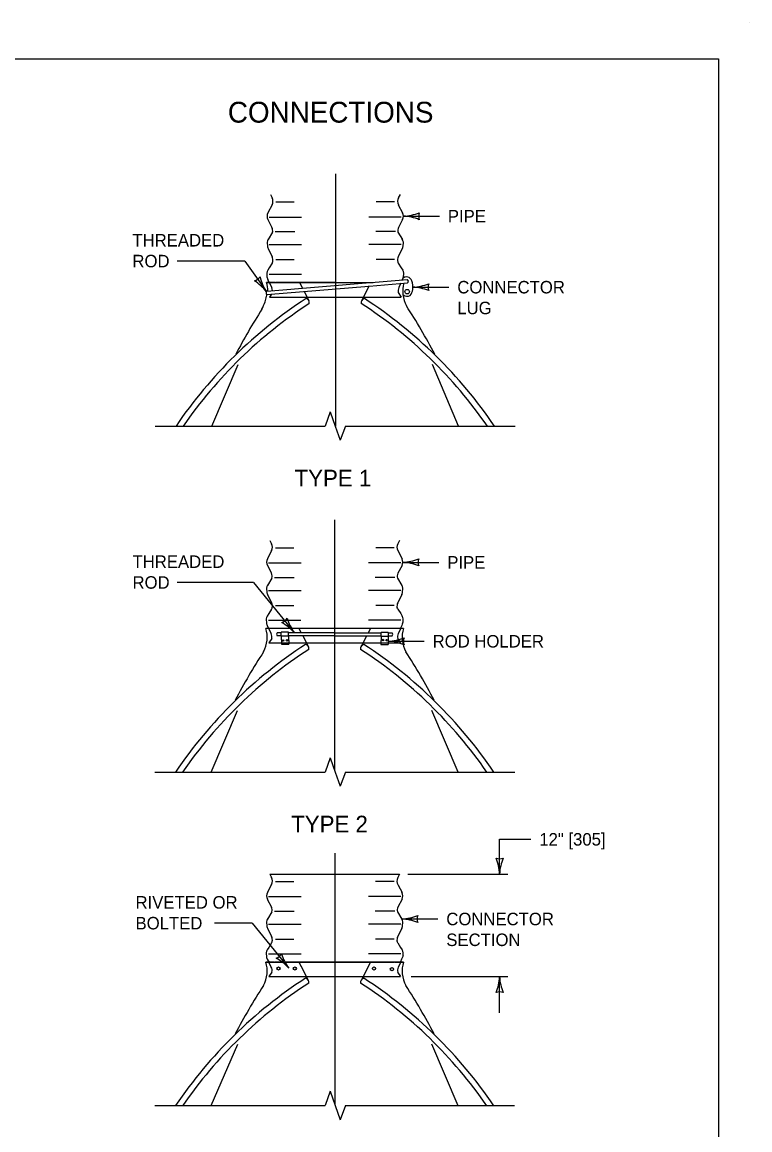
# Model space of a CAD drawing. Extents: x 49991.4 to 50021, y 49987.6 to 50011.4.
# Drawn here: x 50013.4 to 50016.9, y 49993.85 to 49999.18 of the extents above; entities that cross this region are included whole.
import ezdxf

# ---------------------------------------------------------------- set-up
doc = ezdxf.new("R2010")
doc.units = 0
for name, color, linetype in [('Level 1', 7, 'Continuous'), ('Level 2', 7, 'Continuous'), ('Level 3', 7, 'Continuous'), ('Level 4', 7, 'Continuous'), ('Level 5', 7, 'Continuous'), ('Level 6', 7, 'Continuous')]:
    doc.layers.add(name, color=color, linetype=linetype)

msp = doc.modelspace()

# ---------------------------------------------------------------- linework, layer by layer
at = {"layer": 'Level 1'}
for p, q in [((50016.9001, 49999.1756), (50016.9001, 49999.1756)), ((50014.6049, 49998.298), (50014.5842, 49998.2589)), ((50014.5961, 49998.3469), (50014.6049, 49998.3308)), ((50014.6232, 49998.3122), (50014.7113, 49998.3122)), ((50015.1933, 49998.3122), (50015.1048, 49998.3122)), ((50015.2195, 49998.3469), (50015.2111, 49998.3308)), ((50015.2111, 49998.298), (50015.2317, 49998.2589)), ((50014.5842, 49998.2265), (50014.604, 49998.1891)), ((50014.5902, 49998.2388), (50014.7463, 49998.2388)), ((50015.2255, 49998.2388), (50015.0697, 49998.2388)), ((50015.2317, 49998.2265), (50015.2121, 49998.1891)), ((50014.6067, 49998.1655), (50014.5853, 49998.131)), ((50014.6195, 49998.1694), (50014.7132, 49998.1692)), ((50015.1967, 49998.1694), (50015.1031, 49998.1692)), ((50015.2093, 49998.1655), (50015.2309, 49998.131)), ((50014.5854, 49998.0871), (50014.6052, 49998.0475)), ((50014.5902, 49998.107), (50014.746, 49998.107)), ((50015.2255, 49998.107), (50015.0699, 49998.107)), ((50015.2302, 49998.0871), (50015.2111, 49998.0475)), ((50014.6229, 49998.0339), (50014.7111, 49998.0339)), ((50015.1934, 49998.0339), (50015.1048, 49998.0339)), ((50014.5912, 49997.9951), (50014.584, 49997.983)), ((50014.6052, 49998.0165), (50014.5912, 49997.9951)), ((50014.607, 49998.0218), (50014.6078, 49998.024)), ((50015.2089, 49998.0218), (50015.2082, 49998.024)), ((50015.2111, 49998.0165), (50015.2247, 49997.9951)), ((50015.2247, 49997.9951), (50015.2323, 49997.983)), ((50014.5776, 49997.9245), (50015.0795, 49997.9244)), ((50014.5832, 49997.9387), (50014.5903, 49997.9244)), ((50014.5902, 49997.9644), (50014.746, 49997.9644)), ((50015.0803, 49997.9238), (50015.254, 49997.9377)), ((50015.2301, 49997.9387), (50015.2283, 49997.935)), ((50015.2323, 49997.944), (50015.2301, 49997.9387)), ((50015.2363, 49997.9548), (50015.2323, 49997.944)), ((50015.2323, 49997.944), (50015.2323, 49997.944)), ((50014.6183, 49997.9244), (50014.5776, 49997.9244)), ((50014.5776, 49997.9244), (50015.0894, 49997.9244)), ((50014.5793, 49997.8669), (50015.0699, 49997.9068)), ((50014.5798, 49997.8828), (50015.076, 49997.9235)), ((50014.9088, 49997.9244), (50014.6213, 49997.9244)), ((50014.736, 49997.9244), (50014.7506, 49997.8968)), ((50014.7584, 49997.8815), (50014.7815, 49997.8362)), ((50015.0709, 49997.9074), (50015.0344, 49997.8362)), ((50015.0704, 49997.9068), (50015.2553, 49997.9223)), ((50015.076, 49997.9235), (50015.076, 49997.9235)), ((50015.08, 49997.9244), (50015.088, 49997.9244)), ((50014.7724, 49997.854), (50015.0435, 49997.854)), ((50014.3151, 49997.234), (50014.441, 49997.5295)), ((50015.501, 49997.2338), (50015.3747, 49997.5294)), ((50014.5934, 49996.6837), (50014.602, 49996.6675)), ((50014.6204, 49996.6489), (50014.7086, 49996.6489)), ((50015.1905, 49996.6489), (50015.1023, 49996.6489)), ((50015.217, 49996.6837), (50015.2084, 49996.6675)), ((50014.602, 49996.635), (50014.5819, 49996.5957)), ((50015.2084, 49996.635), (50015.2289, 49996.5957)), ((50014.5819, 49996.5634), (50014.6012, 49996.5259)), ((50014.5876, 49996.5756), (50014.7436, 49996.5756)), ((50015.2227, 49996.5756), (50015.067, 49996.5756)), ((50015.2289, 49996.5634), (50015.2094, 49996.5259)), ((50014.604, 49996.5024), (50014.5825, 49996.468)), ((50014.6165, 49996.5063), (50014.7105, 49996.5061)), ((50015.1941, 49996.5063), (50015.1003, 49996.5061)), ((50015.2067, 49996.5024), (50015.2279, 49996.468)), ((50014.5876, 49996.4438), (50014.7436, 49996.4438)), ((50015.2227, 49996.4438), (50015.0672, 49996.4438)), ((50014.5828, 49996.4239), (50014.6023, 49996.3845)), ((50015.2279, 49996.4239), (50015.2082, 49996.3845)), ((50014.5885, 49996.3319), (50014.581, 49996.3199)), ((50014.6023, 49996.3535), (50014.5885, 49996.3319)), ((50014.6047, 49996.3587), (50014.6053, 49996.361)), ((50014.6203, 49996.3708), (50014.7084, 49996.3707)), ((50015.1905, 49996.3708), (50015.1023, 49996.3707)), ((50015.2059, 49996.3587), (50015.2054, 49996.361)), ((50015.2082, 49996.3535), (50015.2224, 49996.3319)), ((50015.2224, 49996.3319), (50015.2296, 49996.3199)), ((50014.5806, 49996.2755), (50014.5875, 49996.2612)), ((50014.5876, 49996.3013), (50014.7434, 49996.3013)), ((50015.2227, 49996.3013), (50015.0672, 49996.3013)), ((50015.2276, 49996.2757), (50015.2213, 49996.2627)), ((50015.2293, 49996.2809), (50015.2276, 49996.2757)), ((50015.2334, 49996.2916), (50015.2293, 49996.2809)), ((50015.2293, 49996.2809), (50015.2293, 49996.2809)), ((50015.2357, 49996.2612), (50014.5749, 49996.2612)), ((50014.6474, 49996.2403), (50014.6295, 49996.2403)), ((50014.6483, 49996.2252), (50014.6295, 49996.2252)), ((50014.6826, 49996.2423), (50014.6481, 49996.2423)), ((50014.6826, 49996.2237), (50014.6481, 49996.2237)), ((50014.6481, 49996.2237), (50014.6492, 49996.186)), ((50014.6826, 49996.2237), (50014.6852, 49996.1859)), ((50014.9065, 49996.2252), (50014.6835, 49996.2252)), ((50014.9055, 49996.2403), (50014.6845, 49996.2403)), ((50014.7335, 49996.2612), (50014.7443, 49996.2403)), ((50014.7518, 49996.2252), (50014.7788, 49996.173)), ((50014.9045, 49996.2252), (50015.0588, 49996.2252)), ((50014.9055, 49996.2403), (50015.1263, 49996.2403)), ((50015.0586, 49996.2252), (50015.0318, 49996.173)), ((50015.0588, 49996.2252), (50015.1276, 49996.2252)), ((50015.0771, 49996.2612), (50015.0663, 49996.2403)), ((50015.1279, 49996.2237), (50015.1271, 49996.1839)), ((50015.1279, 49996.2423), (50015.1629, 49996.2423)), ((50015.1279, 49996.2237), (50015.1629, 49996.2237)), ((50015.1629, 49996.2237), (50015.1622, 49996.1831)), ((50015.1627, 49996.2252), (50015.1812, 49996.2252)), ((50015.1636, 49996.2403), (50015.1812, 49996.2403)), ((50014.6492, 49996.186), (50014.6856, 49996.1857)), ((50014.7695, 49996.1909), (50015.041, 49996.1909)), ((50015.1271, 49996.1839), (50015.1622, 49996.1839)), ((50014.3122, 49995.5705), (50014.438, 49995.8664)), ((50015.4985, 49995.5705), (50015.3722, 49995.8664)), ((50014.5934, 49995.0801), (50015.217, 49995.0801)), ((50014.5938, 49995.0795), (50014.6021, 49995.0635)), ((50015.217, 49995.0801), (50015.2084, 49995.0633)), ((50014.6021, 49995.0309), (50014.582, 49994.9916)), ((50014.6201, 49995.0447), (50014.7085, 49995.0447)), ((50015.1904, 49995.0447), (50015.1021, 49995.0447)), ((50015.2104, 49995.0272), (50015.2288, 49994.9916)), ((50014.5815, 49994.9592), (50014.6009, 49994.9216)), ((50014.5878, 49994.9714), (50014.7436, 49994.9714)), ((50015.2227, 49994.9714), (50015.0672, 49994.9714)), ((50015.2288, 49994.9592), (50015.2093, 49994.9216)), ((50014.6039, 49994.8981), (50014.5827, 49994.8639)), ((50014.6165, 49994.9019), (50014.7101, 49994.9019)), ((50015.194, 49994.9019), (50015.1003, 49994.9019)), ((50015.2066, 49994.8981), (50015.2282, 49994.8639)), ((50014.5878, 49994.8397), (50014.7436, 49994.8397)), ((50015.2227, 49994.8397), (50015.0672, 49994.8397)), ((50014.5827, 49994.8198), (50014.6022, 49994.7804)), ((50015.2278, 49994.8198), (50015.2082, 49994.7804)), ((50014.6022, 49994.7492), (50014.5885, 49994.7275)), ((50014.6045, 49994.7545), (50014.6052, 49994.7563)), ((50014.6201, 49994.7664), (50014.7084, 49994.7664)), ((50015.1904, 49994.7664), (50015.1021, 49994.7664)), ((50015.2059, 49994.7545), (50015.2056, 49994.7563)), ((50015.2082, 49994.7492), (50015.2219, 49994.7275)), ((50014.5885, 49994.7275), (50014.5809, 49994.7155)), ((50014.5878, 49994.6969), (50014.7436, 49994.6969)), ((50015.2227, 49994.6969), (50015.0672, 49994.6969)), ((50015.2219, 49994.7275), (50015.2298, 49994.7155)), ((50015.2292, 49994.6767), (50015.2271, 49994.6713)), ((50015.2336, 49994.6873), (50015.2292, 49994.6767)), ((50015.2292, 49994.6767), (50015.2292, 49994.6767)), ((50014.616, 49994.6572), (50014.5748, 49994.6572)), ((50014.5748, 49994.6572), (50015.1918, 49994.6572)), ((50015.2357, 49994.6572), (50014.6187, 49994.6572)), ((50014.7336, 49994.6572), (50014.7443, 49994.6358)), ((50014.7439, 49994.6371), (50014.7786, 49994.5688)), ((50015.0769, 49994.6572), (50015.0318, 49994.5688)), ((50015.1947, 49994.6572), (50015.2357, 49994.6572)), ((50015.2271, 49994.6713), (50015.2213, 49994.6585)), ((50014.7695, 49994.5868), (50015.041, 49994.5868)), ((50014.3123, 49993.9671), (50014.4391, 49994.2618)), ((50015.4984, 49993.9663), (50015.3722, 49994.2622))]:
    msp.add_line(p, q, dxfattribs=at)
msp.add_lwpolyline([(49999.3835, 49998.9992), (50016.7501, 49998.9992), (50016.7501, 49987.7988), (49999.3835, 49987.7988)], close=True, dxfattribs=at)
for centre, radius in [((50015.2533, 49997.8799), 0.011), ((50014.657, 49996.2031), 0.00375), ((50014.6758, 49996.2038), 0.00375), ((50015.1378, 49996.2052), 0.00375), ((50015.1552, 49996.2045), 0.00375), ((50014.6353, 49994.6258), 0.00763), ((50014.7138, 49994.6258), 0.00763), ((50015.094, 49994.6258), 0.00763), ((50015.1801, 49994.6228), 0.00763)]:
    msp.add_circle(centre, radius, dxfattribs=at)
for centre, radius, start, end in [((50014.5736, 49998.3143), 0.0352, 332.371, 27.6851), ((50015.2424, 49998.3143), 0.0352, 152.3149, 207.629), ((50014.6157, 49998.2427), 0.0352, 152.3604, 207.46), ((50015.2003, 49998.2427), 0.0352, 332.54, 27.6396), ((50014.5723, 49998.1734), 0.0352, 346.8983, 26.3953), ((50015.2437, 49998.1734), 0.0352, 153.6047, 193.1017), ((50014.6157, 49998.1129), 0.0352, 148.1002, 195.4761), ((50014.617, 49998.1029), 0.0352, 179.0002, 206.3871), ((50015.2003, 49998.1129), 0.0352, 344.5239, 31.8998), ((50015.199, 49998.1029), 0.0352, 333.613, 0.9998), ((50014.5735, 49998.032), 0.0352, 346.8983, 26.3953), ((50015.2425, 49998.032), 0.0352, 153.6047, 193.1017), ((50014.6136, 49997.9643), 0.0352, 148.1002, 195.4761), ((50014.5735, 49998.032), 0.0352, 333.8088, 343.22), ((50015.2425, 49998.032), 0.0352, 196.78, 206.1912), ((50015.2024, 49997.9643), 0.0352, 344.5239, 31.8998), ((50014.6149, 49997.9543), 0.0352, 179.0002, 206.3871), ((50015.2505, 49997.9247), 0.0259, 16.8301, 137.3233), ((50015.25, 49997.9297), 0.0092, 304.5117, 64.8853), ((50015.195, 49997.9015), 0.086, 352.6406, 20.9309), ((50014.5858, 49997.8744), 0.0104, 125.5062, 232.8624), ((50014.4342, 49997.8819), 0.1495, 0.1324, 16.4834), ((50014.4304, 49997.8824), 0.1495, 0.1196, 0.1324), ((50015.3818, 49997.8819), 0.1495, 164.8373, 207.8835), ((50015.2323, 49997.8946), 0.0482, 317.2806, 355.0402), ((50015.9737, 49995.9928), 2.2116, 123.0384, 145.8684), ((50015.9737, 49995.9928), 2.1834, 123.0384, 145.3653), ((50014.4304, 49997.8824), 0.1495, 350.4533, 353.7472), ((50014.7632, 49997.8269), 0.0205, 349.5581, 76.5269), ((50015.0528, 49997.8269), 0.0205, 103.4731, 190.4419), ((50013.8423, 49995.9928), 2.1834, 34.6347, 56.9616), ((50013.8423, 49995.9928), 2.2116, 34.1316, 56.9616), ((50015.2523, 49997.8864), 0.0289, 231.0275, 302.1309), ((50016.9089, 49996.2838), 2.7969, 147.2818, 152.4206), ((50012.9071, 49996.2838), 2.7969, 27.5794, 33.1194), ((50014.5709, 49996.6512), 0.0352, 332.371, 27.6851), ((50015.2396, 49996.6512), 0.0352, 152.3149, 207.629), ((50014.613, 49996.5796), 0.0352, 152.3604, 207.46), ((50015.1976, 49996.5796), 0.0352, 332.54, 27.6396), ((50014.5695, 49996.5103), 0.0352, 346.8983, 26.3953), ((50015.241, 49996.5103), 0.0352, 153.6047, 193.1017), ((50014.613, 49996.4498), 0.0352, 148.1002, 195.4761), ((50014.6143, 49996.4398), 0.0352, 179.0002, 206.3871), ((50015.1975, 49996.4498), 0.0352, 344.5239, 31.8998), ((50015.1963, 49996.4398), 0.0352, 333.613, 0.9998), ((50014.5708, 49996.3689), 0.0352, 346.8983, 26.3953), ((50015.2398, 49996.3689), 0.0352, 153.6047, 193.1017), ((50014.5708, 49996.3689), 0.0352, 333.8088, 343.22), ((50015.2398, 49996.3689), 0.0352, 196.78, 206.1912), ((50014.6109, 49996.3012), 0.0352, 148.1002, 195.4761), ((50014.6121, 49996.2912), 0.0352, 179.0002, 206.3871), ((50015.1997, 49996.3012), 0.0352, 344.5239, 31.8998), ((50014.4315, 49996.2188), 0.1495, 332.1165, 16.4834), ((50014.6362, 49996.2328), 0.00996, 132.7323, 227.2677), ((50014.6723, 49996.2329), 0.026, 159.233, 200.767), ((50014.6467, 49996.2329), 0.0372, 345.6586, 14.3414), ((50015.1641, 49996.2329), 0.0372, 165.6586, 194.3414), ((50015.1386, 49996.2329), 0.026, 339.233, 20.767), ((50015.1746, 49996.2328), 0.00996, 312.7323, 47.2677), ((50015.379, 49996.2188), 0.1495, 163.5166, 207.8835), ((50015.971, 49994.3297), 2.2116, 123.0384, 145.8707), ((50014.7604, 49996.1637), 0.0205, 349.5581, 76.5269), ((50015.0501, 49996.1637), 0.0205, 103.4731, 190.4419), ((50013.8396, 49994.3297), 2.2116, 34.1293, 56.9616), ((50015.971, 49994.3297), 2.1834, 123.0384, 145.3677), ((50016.9062, 49994.6207), 2.7969, 146.8806, 152.4206), ((50013.8396, 49994.3297), 2.1834, 34.6323, 56.9616), ((50012.9044, 49994.6207), 2.7969, 27.5794, 33.1194), ((50014.5709, 49995.0469), 0.0352, 332.371, 27.6851), ((50015.2396, 49995.0469), 0.0352, 152.3149, 214.0203), ((50014.6129, 49994.9753), 0.0352, 152.3604, 207.46), ((50015.1975, 49994.9753), 0.0352, 332.54, 27.6396), ((50014.5695, 49994.906), 0.0352, 346.8983, 26.3953), ((50015.241, 49994.906), 0.0352, 153.6047, 193.1017), ((50014.613, 49994.8455), 0.0352, 148.1002, 195.4761), ((50014.6142, 49994.8355), 0.0352, 179.0002, 206.3871), ((50015.1962, 49994.8355), 0.0352, 333.613, 0.9998), ((50015.1981, 49994.8463), 0.0349, 343.0868, 30.4626), ((50014.5707, 49994.7646), 0.0352, 346.8983, 26.3953), ((50014.5707, 49994.7646), 0.0352, 333.8088, 343.22), ((50015.2398, 49994.7646), 0.0352, 153.6047, 193.1017), ((50015.2398, 49994.7646), 0.0352, 196.78, 206.1912), ((50014.6108, 49994.6969), 0.0352, 148.1002, 195.4761), ((50014.6121, 49994.6869), 0.0352, 179.0002, 237.3604), ((50015.1997, 49994.6969), 0.0352, 344.5239, 31.8998), ((50014.4315, 49994.6145), 0.1495, 332.1165, 16.4834), ((50015.379, 49994.6145), 0.1495, 163.5166, 207.8835), ((50015.9709, 49992.7254), 2.2116, 123.0384, 145.843), ((50014.7604, 49994.5595), 0.0205, 349.5581, 76.5269), ((50015.0501, 49994.5595), 0.0205, 103.4731, 190.4419), ((50013.8396, 49992.7254), 2.2116, 34.132, 56.9616), ((50015.9709, 49992.7254), 2.1834, 123.0384, 145.3394), ((50016.9061, 49993.0164), 2.7969, 146.8806, 152.4206), ((50013.8396, 49992.7254), 2.1834, 34.6351, 56.9616), ((50012.9043, 49993.0164), 2.7969, 27.5794, 33.1194)]:
    msp.add_arc(centre, radius, start, end, dxfattribs=at)
msp.add_spline([(50014.5557, 49997.7954), (50014.571, 49997.8314), (50014.5781, 49997.8575)], degree=3, dxfattribs=at)
at = {"layer": 'Level 3'}
for p, q in [((50015.2356, 49998.2427), (50015.409, 49998.2427)), ((50014.4729, 49998.027), (50014.1477, 49998.027)), ((50014.4729, 49998.027), (50014.577, 49997.8799)), ((50015.281, 49997.9015), (50015.4545, 49997.9015)), ((50015.2328, 49996.5786), (50015.4063, 49996.5786)), ((50014.5158, 49996.4819), (50014.1482, 49996.4819)), ((50014.5158, 49996.4819), (50014.7116, 49996.2403)), ((50015.1624, 49996.1991), (50015.3359, 49996.1991)), ((50015.6978, 49995.0801), (50015.6978, 49995.247)), ((50015.6978, 49995.247), (50015.8485, 49995.247)), ((50015.2571, 49995.0801), (50015.7378, 49995.0801)), ((50014.5093, 49994.844), (50014.3278, 49994.844)), ((50014.5093, 49994.844), (50014.6848, 49994.6273)), ((50015.2281, 49994.864), (50015.4016, 49994.864)), ((50015.2721, 49994.5868), (50015.7378, 49994.5868)), ((50015.6978, 49994.4134), (50015.6978, 49994.5868))]:
    msp.add_line(p, q, dxfattribs=at)
for centre, radius, start, end in [((50015.2241, 49998.4754), 0.233, 272.8273, 292.0772), ((50015.3638, 49998.2427), 0.0548, 162.1388, 197.8612), ((50015.2264, 49998.0206), 0.2223, 67.456, 87.6395), ((50014.503, 49997.9845), 0.0548, 287.4334, 323.1557), ((50014.3937, 49997.736), 0.233, 38.1219, 57.3717), ((50014.7636, 49998.0007), 0.2223, 192.7506, 212.9341), ((50015.2695, 49998.1342), 0.233, 272.8273, 292.0772), ((50015.2719, 49997.6794), 0.2223, 67.456, 87.6395), ((50015.4092, 49997.9015), 0.0548, 162.1388, 197.8612), ((50015.2213, 49996.8113), 0.233, 272.8273, 292.0772), ((50015.361, 49996.5786), 0.0548, 162.1388, 197.8612), ((50015.2237, 49996.3565), 0.2223, 67.456, 87.6395), ((50014.6309, 49996.3399), 0.0548, 291.1693, 326.8917), ((50014.5381, 49996.0848), 0.233, 41.8578, 61.1077), ((50014.8899, 49996.3731), 0.2223, 196.4865, 216.67), ((50015.1509, 49996.4318), 0.233, 272.8273, 292.0772), ((50015.1533, 49995.977), 0.2223, 67.456, 87.6395), ((50015.2906, 49996.1991), 0.0548, 162.1388, 197.8612), ((50015.6978, 49995.2084), 0.0548, 252.1388, 287.8612), ((50015.465, 49995.0686), 0.233, 2.8273, 22.0772), ((50015.9199, 49995.071), 0.2223, 157.456, 177.6395), ((50015.2166, 49995.0967), 0.233, 272.8273, 292.0772), ((50015.2189, 49994.6419), 0.2223, 67.456, 87.6395), ((50015.3563, 49994.864), 0.0548, 162.1388, 197.8612), ((50014.6041, 49994.727), 0.0548, 291.142, 326.8643), ((50014.8631, 49994.76), 0.2223, 196.4592, 216.6427), ((50014.5111, 49994.4719), 0.233, 41.8305, 61.0803), ((50015.4756, 49994.596), 0.2223, 337.456, 357.6395), ((50015.9305, 49994.5983), 0.233, 182.8273, 202.0772), ((50015.6978, 49994.4586), 0.0548, 72.1388, 107.8612)]:
    msp.add_arc(centre, radius, start, end, dxfattribs=at)
at = {"layer": 'Level 4'}
for p, q in [((50014.5904, 49997.9244), (50014.603, 49997.8992)), ((50015.2104, 49997.8756), (50015.2246, 49997.854)), ((50015.2237, 49997.92), (50015.2135, 49997.8992)), ((50014.6013, 49997.8685), (50014.5917, 49997.854)), ((50014.5917, 49997.854), (50014.7724, 49997.854)), ((50015.0435, 49997.854), (50015.2246, 49997.854)), ((50014.5879, 49996.2612), (50014.6003, 49996.2361)), ((50015.221, 49996.2569), (50015.2107, 49996.2361)), ((50014.5888, 49996.1909), (50014.7695, 49996.1909)), ((50014.6031, 49996.2125), (50014.5891, 49996.1909)), ((50015.041, 49996.1909), (50015.2221, 49996.1909)), ((50015.2078, 49996.2125), (50015.2221, 49996.1909)), ((50014.5877, 49994.6572), (50014.6001, 49994.6317)), ((50015.2233, 49994.6572), (50015.2109, 49994.6317)), ((50014.603, 49994.608), (50014.589, 49994.5868)), ((50014.589, 49994.5868), (50014.7695, 49994.5868)), ((50015.041, 49994.5868), (50015.2217, 49994.5868)), ((50015.2077, 49994.608), (50015.2217, 49994.5868))]:
    msp.add_line(p, q, dxfattribs=at)
for centre, radius, start, end in [((50014.5714, 49997.8835), 0.0352, 3.7085, 26.3953), ((50015.2449, 49997.8835), 0.0352, 153.6047, 193.1017), ((50014.5687, 49996.2203), 0.0352, 346.8983, 26.3953), ((50015.2423, 49996.2203), 0.0352, 153.6047, 193.1017), ((50014.5847, 49994.6184), 0.0209, 330.173, 43.8109), ((50015.2422, 49994.616), 0.0352, 153.6047, 193.1017)]:
    msp.add_arc(centre, radius, start, end, dxfattribs=at)
at = {"layer": 'Level 5'}
for p, q in [((50014.9085, 49998.4469), (50014.9085, 49997.2326)), ((50014.9054, 49995.5781), (50014.9054, 49996.7837)), ((50014.9057, 49995.1801), (50014.9057, 49993.9739))]:
    msp.add_line(p, q, dxfattribs=at)
at = {"layer": 'Level 6'}
for p, q in [((50014.8838, 49997.3022), (50014.8595, 49997.2337)), ((50014.8838, 49997.3022), (50014.9081, 49997.2337)), ((50014.043, 49997.2337), (50014.8595, 49997.2337)), ((50014.9081, 49997.2337), (50014.9324, 49997.1652)), ((50014.9567, 49997.2337), (50014.9324, 49997.1652)), ((50014.9567, 49997.2337), (50015.773, 49997.2337)), ((50014.8838, 49995.639), (50014.8595, 49995.5705)), ((50014.8838, 49995.639), (50014.9081, 49995.5705)), ((50014.0403, 49995.5705), (50014.8595, 49995.5705)), ((50014.9081, 49995.5705), (50014.9324, 49995.502)), ((50014.9567, 49995.5705), (50014.9324, 49995.502)), ((50014.9567, 49995.5705), (50015.7703, 49995.5705)), ((50014.8838, 49994.0356), (50014.8595, 49993.9671)), ((50014.8838, 49994.0356), (50014.9081, 49993.9671)), ((50014.0408, 49993.9671), (50014.8592, 49993.9671)), ((50014.9081, 49993.9671), (50014.9324, 49993.8986)), ((50014.9567, 49993.9671), (50014.9324, 49993.8986)), ((50014.9567, 49993.9671), (50015.7696, 49993.9671))]:
    msp.add_line(p, q, dxfattribs=at)

# ---------------------------------------------------------------- texts
at = {"layer": 'Level 2'}
for s, height, p in [('CONNECTIONS', 0.1, (50014.3919, 49998.6926)), ('PIPE', 0.06, (50015.449, 49998.2127)), ('THREADED', 0.06, (50013.9334, 49998.097)), ('ROD', 0.06, (50013.9334, 49997.997)), ('CONNECTOR', 0.06, (50015.4945, 49997.8715)), ('LUG', 0.06, (50015.4945, 49997.7715)), ('TYPE 1', 0.08, (50014.7124, 49996.9437)), ('THREADED', 0.06, (50013.9339, 49996.5519)), ('PIPE', 0.06, (50015.4463, 49996.5486)), ('ROD', 0.06, (50013.9339, 49996.4519)), ('ROD HOLDER', 0.06, (50015.3759, 49996.1691)), ('TYPE 2', 0.08, (50014.6962, 49995.2805)), ('12" [305]', 0.06, (50015.8885, 49995.217)), ('RIVETED OR', 0.06, (50013.9484, 49994.914)), ('CONNECTOR', 0.06, (50015.4416, 49994.834)), ('BOLTED', 0.06, (50013.9484, 49994.814)), ('SECTION', 0.06, (50015.4416, 49994.734))]:
    msp.add_text(s, height=height, dxfattribs=at).set_placement(p)

doc.saveas('drawing.dxf')
